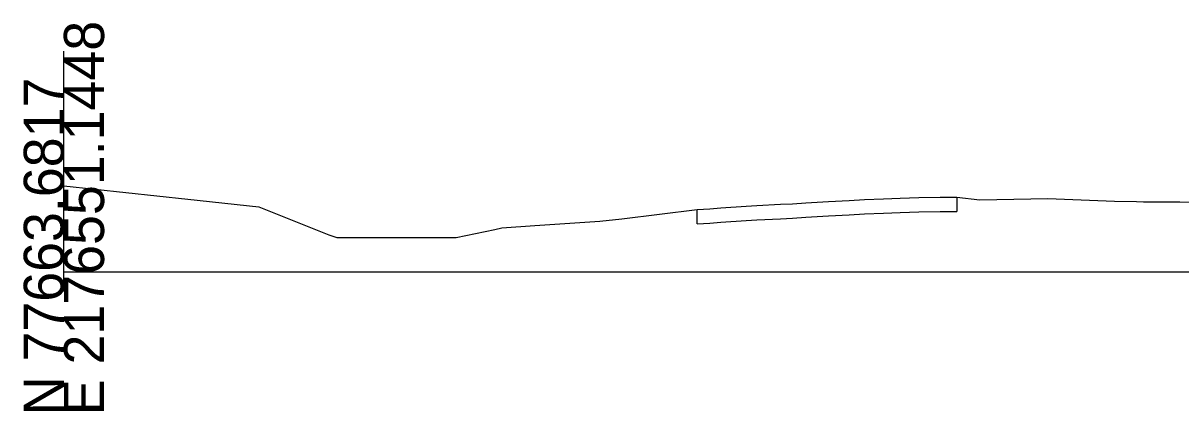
# Model space of a CAD drawing. Extents: x 2177029 to 2201446, y 59897 to 78390.
# Drawn here: x 2200039.9 to 2200120.6, y 65397.6 to 65424.6 of the extents above; entities that cross this region are included whole.
import ezdxf

# ---------------------------------------------------------------- set-up
doc = ezdxf.new("R2010")
doc.units = 0
for name, color, linetype in [('Exist Cross Section Cell', 7, 'Continuous'), ('Exist XS Ground Line', 7, 'Continuous'), ('Old_Level_3', 7, 'Continuous'), ('Prop CMT Pvmt Wedge Surface 1', 7, 'Continuous'), ('Prop CMT Top Wall Envelope', 7, 'Continuous')]:
    doc.layers.add(name, color=color, linetype=linetype)

msp = doc.modelspace()

# ---------------------------------------------------------------- linework, layer by layer
at = {"layer": 'Exist Cross Section Cell'}
msp.add_line((2200042.732, 65407.31), (2200242.732, 65407.31), dxfattribs=at)
at = {"layer": 'Exist XS Ground Line'}
msp.add_lwpolyline([(2200042.732, 65413.29), (2200051.379, 65412.359), (2200056.322, 65411.841), (2200061.197, 65409.885), (2200061.762, 65409.688), (2200062.598, 65409.688), (2200070.071, 65409.688), (2200072.763, 65410.252), (2200073.27, 65410.367), (2200075.556, 65410.528), (2200080.089, 65410.834), (2200081.63, 65410.989), (2200086.885, 65411.637), (2200087.764, 65411.702), (2200088.528, 65411.757), (2200090.285, 65411.872), (2200091.03, 65411.92), (2200092.68, 65412.008), (2200093.533, 65412.052), (2200094.465, 65412.105), (2200096.036, 65412.199), (2200097.471, 65412.277), (2200098.538, 65412.334), (2200099.867, 65412.389), (2200101.041, 65412.436), (2200102.325, 65412.476), (2200103.815, 65412.518), (2200104.986, 65412.515), (2200106.586, 65412.324), (2200111.322, 65412.408), (2200115.968, 65412.235), (2200117.504, 65412.195), (2200117.999, 65412.181), (2200118.427, 65412.187), (2200120.52, 65412.177), (2200126.494, 65412.166)], dxfattribs=at)
at = {"layer": 'Old_Level_3'}
msp.add_line((2200042.732, 65405.938), (2200042.732, 65422.682), dxfattribs=at)
at = {"layer": 'Prop CMT Pvmt Wedge Surface 1'}
for p, q in [((2200104.986, 65412.515), (2200104.986, 65411.515)), ((2200086.885, 65410.637), (2200086.885, 65411.637)), ((2200096.036, 65411.199), (2200097.471, 65411.277)), ((2200097.471, 65411.277), (2200098.538, 65411.334)), ((2200098.538, 65411.334), (2200099.867, 65411.389)), ((2200099.867, 65411.389), (2200101.041, 65411.436)), ((2200101.041, 65411.436), (2200102.325, 65411.476)), ((2200102.325, 65411.476), (2200103.815, 65411.518)), ((2200103.815, 65411.518), (2200104.986, 65411.515)), ((2200086.885, 65410.637), (2200087.764, 65410.702)), ((2200087.764, 65410.702), (2200088.528, 65410.757)), ((2200088.528, 65410.757), (2200090.285, 65410.872)), ((2200090.285, 65410.872), (2200091.03, 65410.92)), ((2200091.03, 65410.92), (2200092.68, 65411.008)), ((2200092.68, 65411.008), (2200093.533, 65411.052)), ((2200093.533, 65411.052), (2200094.465, 65411.105)), ((2200094.465, 65411.105), (2200096.036, 65411.199))]:
    msp.add_line(p, q, dxfattribs=at)

# ---------------------------------------------------------------- texts
at = {"layer": 'Exist Cross Section Cell'}
for s, p in [('E 2176551.1448', (2200045.532, 65397.31)), ('N 77663.6817', (2200042.732, 65397.31))]:
    msp.add_text(s, height=2.8, rotation=90, dxfattribs=at).set_placement(p)
at = {"layer": 'Prop CMT Top Wall Envelope'}
msp.add_text('-', height=0.0001, dxfattribs=at).set_placement((2200042.732, 65407.31))
msp.add_text('-', height=0.0001, dxfattribs=at).set_placement((2200042.732, 65407.31))

doc.saveas('drawing.dxf')
